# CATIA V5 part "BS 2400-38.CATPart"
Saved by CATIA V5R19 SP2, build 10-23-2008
Part number: BS 2400-38
Bounding box of the stored display mesh (mm): x -37.351 to 37.351, y -37.351 to 37.351, z 0 to 121
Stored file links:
  C:\Users\Bora\Desktop\3D Katı model\BS serisi\BS 2400\BS 2400-38.CATPart
  C:\Program Files\Dassault Systemes\B19\intel_a\reffiles\standard\MetricThickPitch.txt
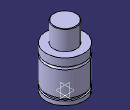
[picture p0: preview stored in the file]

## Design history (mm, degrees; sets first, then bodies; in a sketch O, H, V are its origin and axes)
Body1 (main body)
  Sketch1 on yz-plane, origin (0, 0, 0), H (0, 1, 0), V (0, 0, 1)
    point P1 (22.5, 120)
    point P3 (22.5, 120)
    point P7 (37.5, 66.5)
    point P9 (37.5, 66.5)
    point P10 (37.5, 61.5)
    point P14 (37.5, 61.5)
    line L1 (22.5, 120) -> (22.5, 82)
    arc A1 centre (21.5, 120) radius 1 from (22.5, 120) to (21.5, 121) ccw
    line L2 (37.5, 0) -> (37.5, 8)
    line L3 (37.5, 66.5) -> (37.5, 82)
    arc A2 centre (37.5, 64) radius 2.5 from (37.5, 66.5) to (37.5, 61.5) ccw
    line L4 (34.5, 13) -> (34.5, 8)
    line L5 (37.5, 13) -> (37.5, 61.5)
    line L6 (21.5, 121) -> (0, 121)
    point P15 (0, 121)
    line L7 (22.5, 82) -> (37.5, 82)
    line L8 (0, 0) -> (37.5, 0)
    line L9 (34.5, 13) -> (37.5, 13)
    line L10 (34.5, 8) -> (37.5, 8)
    coincidence: P15 V, P1 P3, P7 P9, P10 P14
    tangency: L6 A1
    horizontal: L7 H, L8 H, L9 H, L10 H
  Shaft1: profile Sketch1, axis Sketch1.V, angle 360
  Sketch2 on face of Shaft1 from Sketch1.L8, origin (0, 0, 0), H (1, 0, 0), V (0, -1, 0)
    point P1 (20, 0)
    distance P1 V = 20
  Hole1: placed by Sketch2, at (20, 0, 0) direction (0, 0, 1), diameter 6.647, depth 5, threaded "M8", thread diameter 8, thread depth 5, pitch 1.25
  CircPattern1: of Hole1, instances 4, angular step 90, axis from xy-plane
